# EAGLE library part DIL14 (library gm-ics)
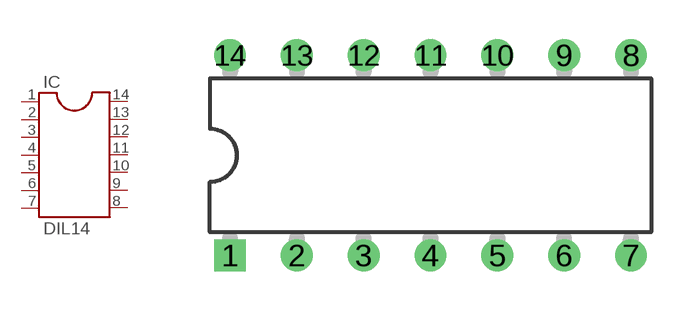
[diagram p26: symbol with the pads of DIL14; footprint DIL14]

Designator prefix IC

## DIL14  [DIL14]
1  1  pas
2  2  pas
3  3  pas
4  4  pas
5  5  pas
6  6  pas
7  7  pas
8  8  pas
9  9  pas
10  10  pas
11  11  pas
12  12  pas
13  13  pas
14  14  pas

## Footprint DIL14 (pad centres in mm)
Dual In Line Package
drill 0.7 square: 1 -7.62,-3.81
drill 0.7 round: 2 -5.08,-3.81; 3 -2.54,-3.81; 4 0,-3.81; 5 2.54,-3.81; 6 5.08,-3.81; 7 7.62,-3.81; 8 7.62,3.81; 9 5.08,3.81; 10 2.54,3.81; 11 0,3.81; 12 -2.54,3.81; 13 -5.08,3.81; 14 -7.62,3.81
